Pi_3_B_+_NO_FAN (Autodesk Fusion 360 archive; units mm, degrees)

design "Pi_3_B_+_NO_FAN" references "Pi 3 B + NO_FAN"
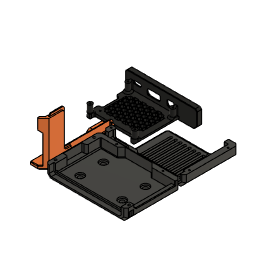
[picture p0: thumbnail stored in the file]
external_derived "ExternalDerived1" bodies "BOTTOM", "Body4", "TOP (1)", "PI3 A/B_MOUNT  (1) (2)"
derived_instance "DerivedInstance1"
derived_instance "DerivedInstance2"
derived_instance "DerivedInstance3"
derived_instance "DerivedInstance1"
derived_instance "DerivedInstance1"
derived_instance "DerivedInstance2"
derived_base_feature "Derived Base Feature1" bodies "BOTTOM"
hole "Hole2" HoleDepth 5 named "d222_1" HoleDiameter 5.3 named "d223_1" CBDepth 2 named "d225_1" CBDiameter 10 named "d226_1" RefDim1 25 named "d227_1" RefDim2 20 named "d228_1"
hole "Hole4" HoleDepth 5 named "d240_1" HoleDiameter 5.3 named "d241_1" CBDepth 2 named "d243_1" CBDiameter 10 named "d244_1" RefDim1 20 named "d245_1" RefDim2 25 named "d246_1"
rectangular_pattern "R-Pattern2" uSpaceDistance 30 named "d249_1" vSpaceDistance 0 named "d250_1"
rectangular_pattern "R-Pattern3" uSpaceDistance 30 named "d253_1" vSpaceDistance 0 named "d254_1"
step "Arrange" envelopeLength 180 envelopeWidth 180 envelopeSeparation 0 separation 5 padding 5 offset 0
extrude "Extrude1" cut of existing geometry blind -1.6248
offset_faces "OffsetFaces1" distance -2.302
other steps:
derived_base_feature "Derived Base Feature1"
derived_base_feature "Derived Base Feature1"
derived_base_feature "Derived Base Feature1" bodies "BOTTOM"
derived_base_feature "Derived Base Feature1" bodies "Body4"
derived_base_feature "Derived Base Feature1" bodies "TOP (1)"
derived_base_feature "Derived Base Feature1" bodies "PI3 A/B_MOUNT  (1) (2)"
create_component "CreateComponent1"
create_component "CreateComponent2"
create_component "CreateComponent3"
create_component "CreateComponent4"
create_component "CreateComponent5"
create_component "CreateComponent6"
create_component "CreateComponent7"
named bodies: "TOP (1)", "BOTTOM", "PI3 A/B_MOUNT  (1) (2)", "Body4"

design "Pi 3 B + NO_FAN"
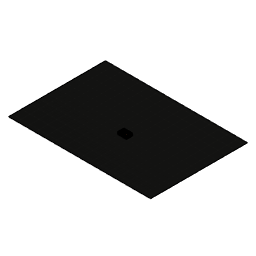
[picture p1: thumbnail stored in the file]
description: arrangementsContainer
base_feature "Base Feature1" bodies "TOP"
base_feature "Base Feature1" bodies "BOTTOM"
base_feature "Base Feature1"
base_feature "Base Feature1"
base_feature "Base Feature1"
base_feature "Base Feature1"
base_feature "Base Feature1"
base_feature "Base Feature1"
base_feature "Base Feature1"
base_feature "Base Feature1"
position "Position1"
sketch "Sketch1" plane through (0, 0, 0) normal (0, 0, 1) x axis (1, 0, 0)
  line L1 (753.1049, -468.8034) -> (-832.4959, -468.8034)
  line L2 (753.1049, 612.7156) -> (753.1049, -468.8034)
  line L3 (-832.4959, 612.7156) -> (753.1049, 612.7156)
  line L4 (-832.4959, -468.8034) -> (-832.4959, 612.7156)
  horizontal L1
  vertical L2
  horizontal L3
  vertical L4
extrude "Extrude1" new body sketch "Sketch1" against normal blind 1
base_feature "Base Feature1" bodies "PI3 A/B_MOUNT  (1) (2)"
component_from_bodies "Body->Comp1"
step "Arrange1" envelopeLength 180 named "d2_1" envelopeWidth 180 envelopeSeparation 0 separation 5 padding 5 offset 0 bodies "TOP"
base_feature "Base Feature1"
position "Position2"
position "Position3"
delete_face "DeleteFace1"
base_feature "Base Feature1" bodies "PI_ZERO_MOUNT_1"
move_face "MoveFace1"
work_plane "WorkPlane2"
split "Split1" bodies "TOP (1)"
move "Move1"
move "Move2"
position "Position4"
align "Align1"
move "Move3"
extrude "Extrude1" add of existing geometry blind 24.193 bodies "TOP (1)"
delete_face "DeleteFace2"
delete_face "DeleteFace3"
delete_face "DeleteFace4"
align "Align1"
work_plane "WorkPlane3"
split "Split1" bodies "BOTTOM (1)"
move "Move1"
align "Align2"
move "Move2"
move "Move3"
extrude "Extrude1" add of existing geometry blind 20.9455 bodies "BOTTOM (1)"
work_plane "WorkPlane4"
split "Split2" bodies "BOTTOM (1)"
delete_face "DeleteFace1"
move "Move4"
split "Split2"
move "Move4"
align "Align3"
align "Align4"
align "Align1"
align "Align1"
delete_face "DeleteFace2"
delete_face "DeleteFace3"
extrude "Extrude2" add of existing geometry blind 28.705 bodies "BOTTOM (1)"
extrude "Extrude2" add of existing geometry blind 27.166 bodies "TOP"
extrude "Extrude3" add of existing geometry blind 29.088
align "Align1"
align "Align2"
align "Align3"
align "Align1"
align "Align1"
align "Align1"
align "Align1"
align "Align1"
work_plane "WorkPlane5" AlongDistance -25
split "Split1"
align "Align4"
extrude "Extrude1" add of existing geometry blind 20.935
move_face "MoveFace1"
move_face "MoveFace2"
move_face "MoveFace2"
delete_face "DeleteFace1"
delete_face "DeleteFace2"
sketch "Sketch3" plane through (0, 0, 18.6752) normal (0, 0, -1) x axis (1, 0, 0)
  line L1 (-40.9922, -30.131) -> (-40.9922, 26.269)
  line L2 (-39.8593, -30.131) -> (-40.9922, -30.131)
  line L3 (-39.8593, -21.931) -> (-39.8593, -30.131)
  line L4 (-37.6593, -19.731) -> (-39.8593, -21.931)
  line L5 (37.1513, -19.731) -> (-37.6593, -19.731)
  line L6 (37.9797, -18.9025) -> (37.1513, -19.731)
  line L7 (37.9797, 16.5519) -> (37.9797, -18.9025)
  line L8 (40.6719, 19.2441) -> (37.9797, 16.5519)
  line L9 (40.6719, 26.269) -> (40.6719, 19.2441)
  line L10 (4.9368, 26.269) -> (40.6719, 26.269)
  line L11 (6.4368, -14.231) -> (6.4368, 24.769)
  line L12 (3.4368, 24.769) -> (3.4368, -14.231)
  line L13 (-0.0632, 26.269) -> (4.9368, 26.269)
  line L14 (1.4368, -14.231) -> (1.4368, 24.769)
  line L15 (-1.5632, 24.769) -> (-1.5632, -14.231)
  line L16 (-5.0632, 26.269) -> (-0.0632, 26.269)
  line L17 (-3.5632, -15.231) -> (-3.5632, 24.769)
  line L18 (-6.5632, 24.769) -> (-6.5632, -15.231)
  line L19 (-10.0633, 26.269) -> (-5.0632, 26.269)
  line L20 (-9.9796, 26.2667) -> (-9.9797, 26.2667)
  line L21 (-8.5632, -17.231) -> (-8.5632, 24.769)
  line L22 (-9.9797, -18.7286) -> (-9.9796, -18.7286)
  line L23 (-11.5633, 24.769) -> (-11.5633, -17.231)
  line L24 (-15.0633, 26.269) -> (-10.0633, 26.269)
  line L25 (-13.5633, -17.231) -> (-13.5633, 24.769)
  line L26 (-16.5633, 24.769) -> (-16.5633, -17.231)
  line L27 (-20.0633, 26.269) -> (-15.0633, 26.269)
  line L28 (-18.5633, -15.231) -> (-18.5633, 24.769)
  line L29 (-21.5633, 24.769) -> (-21.5633, -15.231)
  line L30 (-25.0633, 26.269) -> (-20.0633, 26.269)
  line L31 (-23.5633, -14.231) -> (-23.5633, 24.769)
  line L32 (-26.5633, 24.769) -> (-26.5633, -14.231)
  line L33 (-30.0633, 26.269) -> (-25.0633, 26.269)
  line L34 (-28.5633, -14.231) -> (-28.5633, 24.769)
  line L35 (-31.5633, 24.769) -> (-31.5633, -14.231)
  line L36 (-35.0633, 26.269) -> (-30.0633, 26.269)
  line L37 (-33.5633, -14.231) -> (-33.5633, 24.769)
  line L38 (-36.5633, 24.769) -> (-36.5633, -14.231)
  line L39 (-40.9922, 26.269) -> (-35.0633, 26.269)
  line L40 (-32.6085, -18.7224) -> (10.2712, -18.7224)
  line L41 (-32.6085, 24.769) -> (-32.6085, -18.7224)
  line L42 (10.2712, 24.769) -> (-32.6085, 24.769)
  line L43 (10.2712, -18.7224) -> (10.2712, 24.769)
  arc A1 centre (4.9368, 24.769) radius 1.5 clockwise from (4.9368, 26.269) to (6.4368, 24.769)
  arc A2 centre (4.9368, -14.231) radius 1.5 clockwise from (6.4368, -14.231) to (3.4368, -14.231)
  arc A3 centre (4.9368, 24.769) radius 1.5 clockwise from (3.4368, 24.769) to (4.9368, 26.269)
  arc A4 centre (-0.0632, 24.769) radius 1.5 clockwise from (-0.0632, 26.269) to (1.4368, 24.769)
  arc A5 centre (-0.0632, -14.231) radius 1.5 clockwise from (1.4368, -14.231) to (-1.5632, -14.231)
  arc A6 centre (-0.0632, 24.769) radius 1.5 clockwise from (-1.5632, 24.769) to (-0.0632, 26.269)
  arc A7 centre (-5.0632, 24.769) radius 1.5 clockwise from (-5.0632, 26.269) to (-3.5632, 24.769)
  arc A8 centre (-5.0632, -15.231) radius 1.5 clockwise from (-3.5632, -15.231) to (-6.5632, -15.231)
  arc A9 centre (-5.0632, 24.769) radius 1.5 clockwise from (-6.5632, 24.769) to (-5.0632, 26.269)
  arc A10 centre (-10.0633, 24.769) radius 1.5 clockwise from (-10.0633, 26.269) to (-9.9797, 26.2667)
  arc A11 centre (-10.0632, 24.769) radius 1.5 clockwise from (-9.9796, 26.2667) to (-8.5632, 24.769)
  arc A12 centre (-10.0632, -17.231) radius 1.5 clockwise from (-8.5632, -17.231) to (-9.9796, -18.7286)
  arc A13 centre (-10.0633, -17.231) radius 1.5 clockwise from (-9.9797, -18.7286) to (-11.5633, -17.231)
  arc A14 centre (-10.0633, 24.769) radius 1.5 clockwise from (-11.5633, 24.769) to (-10.0633, 26.269)
  arc A15 centre (-15.0633, 24.769) radius 1.5 clockwise from (-15.0633, 26.269) to (-13.5633, 24.769)
  arc A16 centre (-15.0633, -17.231) radius 1.5 clockwise from (-13.5633, -17.231) to (-16.5633, -17.231)
  arc A17 centre (-15.0633, 24.769) radius 1.5 clockwise from (-16.5633, 24.769) to (-15.0633, 26.269)
  arc A18 centre (-20.0633, 24.769) radius 1.5 clockwise from (-20.0633, 26.269) to (-18.5633, 24.769)
  arc A19 centre (-20.0633, -15.231) radius 1.5 clockwise from (-18.5633, -15.231) to (-21.5633, -15.231)
  arc A20 centre (-20.0633, 24.769) radius 1.5 clockwise from (-21.5633, 24.769) to (-20.0633, 26.269)
  arc A21 centre (-25.0633, 24.769) radius 1.5 clockwise from (-25.0633, 26.269) to (-23.5633, 24.769)
  arc A22 centre (-25.0633, -14.231) radius 1.5 clockwise from (-23.5633, -14.231) to (-26.5633, -14.231)
  arc A23 centre (-25.0633, 24.769) radius 1.5 clockwise from (-26.5633, 24.769) to (-25.0633, 26.269)
  arc A24 centre (-30.0633, 24.769) radius 1.5 clockwise from (-30.0633, 26.269) to (-28.5633, 24.769)
  arc A25 centre (-30.0633, -14.231) radius 1.5 clockwise from (-28.5633, -14.231) to (-31.5633, -14.231)
  arc A26 centre (-30.0633, 24.769) radius 1.5 clockwise from (-31.5633, 24.769) to (-30.0633, 26.269)
  arc A27 centre (-35.0633, 24.769) radius 1.5 clockwise from (-35.0633, 26.269) to (-33.5633, 24.769)
  arc A28 centre (-35.0633, -14.231) radius 1.5 clockwise from (-33.5633, -14.231) to (-36.5633, -14.231)
  arc A29 centre (-35.0633, 24.769) radius 1.5 clockwise from (-36.5633, 24.769) to (-35.0633, 26.269)
  horizontal L40
  vertical L41
  horizontal L42
  vertical L43
extrude "Extrude4" add sketch "Sketch3" profile of L11 A2 L12 L14 A5 L15 L17 A8 L18 L21 A12 A13 L23 L25 A16 L26 L28 A19 L29 L31 A22 L32 L34 A25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 against normal blind 3
delete_face "DeleteFace3"
delete_face "DeleteFace4"
delete_face "DeleteFace5"
delete_face "DeleteFace6"
delete_face "DeleteFace7"
delete_face "DeleteFace8"
rectangular_pattern "R-Pattern1" uSpaceDistance 6 vSpaceDistance 0
position "Position5"
work_plane "WorkPlane6" AlongDistance 2
work_plane "WorkPlane7" AlongDistance 2
move_face "MoveFace1"
move_face "MoveFace2"
move_face "MoveFace3"
hole "Hole1" HoleDepth 10 HoleDiameter 2 RefDim1 3 RefDim2 20
work_axis "WorkAxis1"
move_face "MoveFace4"
work_axis "WorkAxis3"
move_face "MoveFace3"
rectangular_pattern "R-Pattern1" uSpaceDistance 60 vSpaceDistance 0
position "Position6"
position "Position7"
delete_face "DeleteFace1"
delete_face "DeleteFace2"
delete_face "DeleteFace3"
extrude "Extrude2" cut of existing geometry blind -5
delete_face "DeleteFace4"
offset_faces "OffsetFaces1" distance -3.933
offset_faces "OffsetFaces2" distance -1
move_face "MoveFace4"
delete_face "DeleteFace5"
delete_face "DeleteFace4"
delete_face "DeleteFace5"
delete_face "DeleteFace6"
offset_faces "OffsetFaces1" distance -3
delete_face "DeleteFace7"
chamfer "Chamfer2" distance 1
work_plane "WorkPlane8" AlongDistance 1
move_face "MoveFace2"
move_face "MoveFace5"
work_plane "WorkPlane9" AlongDistance 0
sketch "Sketch4" plane through (0, 0, 16.7) normal (0, 0, 1) x axis (-1, 0, 0)
  line L1 (-45.1398, 29) -> (-45.1398, 24.4)
  line L2 (-45.7598, 29) -> (-45.1398, 29)
  line L3 (-45.7598, 35) -> (-45.7598, 29)
  line L4 (-49.1398, 35) -> (-45.7598, 35)
  line L5 (-52.1398, 32) -> (-49.1398, 35)
  line L6 (-52.1398, 21.7542) -> (-52.1398, 32)
  line L7 (-49.1398, 20) -> (-49.1398, 25)
  line L8 (-52.1398, -32) -> (-52.1398, 22.2)
  line L9 (-52.1398, 20) -> (-49.1398, 20)
  line L10 (-45.1398, 20) -> (-45.1398, 24.4)
  line L11 (-49.1398, 20) -> (-45.1398, 20)
  circle C1 centre (-49.1398, 25) radius 1.4
  arc A1 centre (-49.1398, 24.4) radius 4 clockwise from (-45.1398, 24.4) to (-52.1398, 21.7542)
  point P2 (-49.1398, 25)
  point P11 (-49.1398, 25)
  point P15 (-52.1398, 20)
  point P3 (-45.1398, 24.4)
  point P16 (-45.1398, 24.4)
  point P12 (-49.1398, 20)
  coincident P2 P11
  vertical L7
  coincident L8 P15
  perpendicular L8 L9
  coincident P3 P16
  perpendicular L9 L10
  perpendicular L7 L11
  dimension "d48" distance P11 P12 = 5
extrude "Extrude3" add sketch "Sketch4" profile of A1 L7 L10 L11 against normal blind 11.7
offset_faces "OffsetFaces2" distance 3
delete_face "DeleteFace8"
delete_face "DeleteFace9"
move_face "MoveFace6"
delete_face "DeleteFace10"
delete_face "DeleteFace11"
delete_face "DeleteFace12"
move_face "MoveFace7"
work_axis "WorkAxis4"
move_face "MoveFace4"
offset_faces "OffsetFaces1" distance -1.4
chamfer "Chamfer2" distance 3
fillet "Fillet1" radius 2
offset_faces "OffsetFaces3" distance 1.4
offset_faces "OffsetFaces3" distance -1
offset_faces "OffsetFaces4" distance 1
position "Position8"
offset_faces "OffsetFaces1" distance -1
offset_faces "OffsetFaces5" distance -0.4
offset_faces "OffsetFaces3" distance -1.053
sketch "Sketch5" plane through (0, -27, 0) normal (0, 1, 0) x axis (-1, 0, 0)
  line L1 (-40.8321, 30.4) -> (-13.0969, 30.4)
  line L2 (-45.1398, 26.0922) -> (-40.8321, 30.4)
  line L3 (-45.1398, 24.753) -> (-45.1398, 26.0922)
  line L4 (-41.3928, 28.5) -> (-45.1398, 24.753)
  line L5 (39.9036, 28.5) -> (-41.3928, 28.5)
  line L6 (45.1398, 23.2638) -> (39.9036, 28.5)
  line L7 (45.1398, 26.0922) -> (45.1398, 23.2638)
  line L8 (40.8321, 30.4) -> (45.1398, 26.0922)
  line L9 (34.9031, 30.4) -> (40.8321, 30.4)
  line L10 (28.9031, 30.4) -> (34.9031, 30.4)
  line L11 (22.9031, 30.4) -> (28.9031, 30.4)
  line L12 (16.9031, 30.4) -> (22.9031, 30.4)
  line L13 (10.9031, 30.4) -> (16.9031, 30.4)
  line L14 (4.9031, 30.4) -> (10.9031, 30.4)
  line L15 (-1.0969, 30.4) -> (4.9031, 30.4)
  line L16 (-7.0969, 30.4) -> (-1.0969, 30.4)
  line L17 (-13.0969, 30.4) -> (-7.0969, 30.4)
  line L18 (-21.1686, 27.0881) -> (-42.8047, 27.0881)
  line L19 (-21.0388, 27.4) -> (-20.0388, 28.4)
  line L20 (-20.5388, 27.9) -> (-20.0388, 28.4)
  line L21 (-22.4602, 25.9787) -> (-20.5388, 27.9)
  line L22 (-21.0388, 27.4) -> (-22.4602, 25.9787)
  line L23 (-45.1398, 24.753) -> (-41.3928, 28.5)
  line L24 (39.9036, 28.5) -> (-41.3928, 28.5)
  line L25 (-41.4928, 28.4) -> (-20.0388, 28.4)
  point P19 (-42.8047, 27.0881)
  point P21 (-20.0388, 28.4)
  point P28 (-20.0388, 28.4)
  point P29 (-41.4928, 28.4)
  coincident L4 P19
  parallel L5 L18
  coincident P21 P28
  coincident L23 P29
  parallel L24 L25
extrude "Extrude5" add sketch "Sketch5" profile of L4 L18 L19 L20 L21 L22 L23 L25 against normal blind 2
offset_faces "OffsetFaces4" distance 0.172
offset_faces "OffsetFaces5" distance -5
delete_face "DeleteFace9"
offset_faces "OffsetFaces6" distance -2
offset_faces "OffsetFaces7" distance -1
chamfer "Chamfer3" distance 2.5
offset_faces "OffsetFaces6" distance -1
move_face "MoveFace3"
move_face "MoveFace4"
move_face "MoveFace5"
position "Position9"
offset_faces "OffsetFaces4" distance 0.4
sketch "Sketch6" plane through (0, -24.4, 0) normal (0, 1, 0) x axis (-1, 0, 0)
  line L1 (-44.9031, 33.4) -> (-40.0398, 33.4)
  line L2 (-52.1398, 26.1633) -> (-44.9031, 33.4)
  line L3 (-52.1398, 16.7) -> (-52.1398, 26.1633)
  line L4 (-47.1398, 16.7) -> (-52.1398, 16.7)
  line L5 (-47.1398, 26.9206) -> (-47.1398, 16.7)
  line L6 (-43.6605, 30.4) -> (-47.1398, 26.9206)
  line L7 (-38.1398, 30.4) -> (-43.6605, 30.4)
  line L8 (-38.1398, 31.6) -> (-38.1398, 30.4)
  line L9 (-40.0398, 31.6) -> (-38.1398, 31.6)
  line L10 (-40.0398, 33.4) -> (-40.0398, 31.6)
  line L11 (-51.3825, 26.9206) -> (-47.1398, 26.9206)
  line L12 (-47.1398, 29.0252) -> (-42.2068, 29.0252)
  line L13 (-49.2779, 29.0252) -> (-47.1398, 29.0252)
  line L14 (-49.2779, 29.0252) -> (-49.2779, 29.0252)
  line L15 (-42.2068, 29.0252) -> (-49.2779, 29.0252)
  line L16 (-42.2068, 29.0252) -> (-42.2068, 29.0252)
  point P7 (-47.1398, 26.9206)
  point P12 (-47.1398, 26.9206)
  point P13 (-51.3825, 26.9206)
  coincident P7 P12
  coincident L2 P13
  perpendicular L5 L11
extrude "Extrude2" new body sketch "Sketch6" profile of L2 L6 L11 L12 L13 L15 blind 15 from offset 0.1
combine "Combine1"
chamfer "Chamfer3" distance 2
delete_face "DeleteFace6"
offset_faces "OffsetFaces5" distance 0.75
extrude "Extrude3" add of existing geometry blind 1
delete_face "DeleteFace7"
offset_faces "OffsetFaces6" distance -1
extrude "Extrude4" add of existing geometry blind 1
delete_face "DeleteFace8"
delete_face "DeleteFace9"
delete_face "DeleteFace10"
chamfer "Chamfer5" distance 0.75
delete_face "DeleteFace11"
delete_face "DeleteFace12"
delete_face "DeleteFace13"
chamfer "Chamfer6" distance 0.75
offset_faces "OffsetFaces7" distance 0.8
delete_face "DeleteFace14"
chamfer "Chamfer4" distance 0.75
chamfer "Chamfer7" distance 0.75
split "Split3" bodies "TOP (1) (1)", "TOP (1) (2)"
chamfer "Chamfer5" distance 0.75
combine "Combine1" bodies "TOP (1) (1)", "TOP (1) (2)"
draft "Draft1" "d90" 45 (= "Angle1") "d91" 0 (= "Angle2")
combine "Combine2"
offset_faces "OffsetFaces7" distance 0.2
offset_faces "OffsetFaces8" distance -0.2
move_face "MoveFace5"
move_face "MoveFace5"
offset_faces "OffsetFaces9" distance -0.1
chamfer "Chamfer8" distance 2
chamfer "Chamfer3" distance 2
sketch "Sketch7" plane through (0, -24.3, 0) normal (0, -1, 0) x axis (1, 0, 0)
  line L1 (25.1398, 30.4) -> (25.1398, 31.6)
  line L2 (40.8321, 30.4) -> (25.1398, 30.4)
  line L3 (41.2068, 30.0252) -> (40.8321, 30.4)
  line L4 (44.0353, 30.0252) -> (41.2068, 30.0252)
  line L5 (45.0353, 29.0252) -> (44.0353, 30.0252)
  line L6 (47.8898, 26.1706) -> (45.0353, 29.0252)
  line L7 (47.8898, 25.1706) -> (47.8898, 26.1706)
  line L8 (51.3825, 25.1706) -> (47.8898, 25.1706)
  line L9 (52.1325, 25.9206) -> (51.3825, 25.1706)
  line L10 (52.1325, 26.1706) -> (52.1325, 25.9206)
  line L11 (44.9031, 33.4) -> (52.1325, 26.1706)
  line L12 (27.0398, 33.4) -> (44.9031, 33.4)
  line L13 (27.0398, 31.6) -> (27.0398, 33.4)
  line L14 (25.1398, 31.6) -> (27.0398, 31.6)
  line L15 (40.1398, 31.6) -> (25.1398, 31.6)
  line L16 (40.1398, 30.4) -> (40.1398, 31.6)
  line L17 (25.1398, 30.4) -> (40.1398, 30.4)
  line L18 (25.1398, 31.6) -> (25.1398, 30.4)
  point P2 (25.1398, 31.6)
  point P16 (25.1398, 31.6)
  point P17 (40.1398, 31.6)
  horizontal L15
  vertical L16
  horizontal L17
  vertical L18
  coincident P2 P16
  dimension "d97" distance P16 P17 = 15
extrude "Extrude5" add sketch "Sketch7" profile of L1 L2 L14 L15 L16 L17 L18 along normal blind 2
delete_face "DeleteFace15"
delete_face "DeleteFace16"
delete_face "DeleteFace17"
delete_face "DeleteFace18"
offset_faces "OffsetFaces8" distance 0.6
chamfer "Chamfer10" distance 2.6
combine "Combine2"
offset_faces "OffsetFaces10" distance -0.1
offset_faces "OffsetFaces9" distance 2
combine "Combine3"
offset_faces "OffsetFaces11" distance -0.1
offset_faces "OffsetFaces12" distance -0.1
offset_faces "OffsetFaces13" distance -0.1
sketch "Sketch8" plane through (0, -27, 0) normal (0, 1, 0) x axis (-1, 0, 0)
  line L1 (-40.4097, 31.7) -> (-25.0398, 31.7)
  line L2 (-40.4097, 30.4) -> (-40.4097, 31.7)
  line L3 (-43.6605, 30.4) -> (-40.4097, 30.4)
  line L4 (-45.1398, 28.9206) -> (-43.6605, 30.4)
  line L5 (-45.1398, 26.1672) -> (-45.1398, 28.9206)
  line L6 (-44.2189, 27.0881) -> (-45.1398, 26.1672)
  line L7 (-28.4218, 27.0881) -> (-44.2189, 27.0881)
  line L8 (-27.0099, 28.5) -> (-28.4218, 27.0881)
  line L9 (39.9036, 28.5) -> (-27.0099, 28.5)
  line L10 (45.1398, 23.2638) -> (39.9036, 28.5)
  line L11 (45.1398, 26.0922) -> (45.1398, 23.2638)
  line L12 (40.8321, 30.4) -> (45.1398, 26.0922)
  line L13 (34.9031, 30.4) -> (40.8321, 30.4)
  line L14 (28.9031, 30.4) -> (34.9031, 30.4)
  line L15 (22.9031, 30.4) -> (28.9031, 30.4)
  line L16 (16.9031, 30.4) -> (22.9031, 30.4)
  line L17 (10.9031, 30.4) -> (16.9031, 30.4)
  line L18 (4.9031, 30.4) -> (10.9031, 30.4)
  line L19 (-1.0969, 30.4) -> (4.9031, 30.4)
  line L20 (-7.0969, 30.4) -> (-1.0969, 30.4)
  line L21 (-13.0969, 30.4) -> (-7.0969, 30.4)
  line L22 (-25.0398, 30.4) -> (-13.0969, 30.4)
  line L23 (-25.0398, 31.7) -> (-25.0398, 30.4)
  line L24 (-18.6605, 30.4) -> (-43.6605, 30.4)
  line L25 (-18.6605, 28.5) -> (-18.6605, 30.4)
  line L26 (-45.5605, 28.5) -> (-18.6605, 28.5)
  line L27 (-43.6605, 30.4) -> (-45.5605, 28.5)
  point P5 (-43.6605, 30.4)
  point P25 (-43.6605, 30.4)
  point P27 (-18.6605, 28.5)
  point P26 (-18.6605, 30.4)
  coincident P5 P25
  parallel L22 L24
  coincident L9 P27
  perpendicular L9 L25
  perpendicular L5 L26
  parallel L4 L27
  dimension "d108" distance P25 P26 = 25
extrude "Extrude6" add sketch "Sketch8" profile of L3 L4 L5 L9 L22 L24 L25 L26 L27 along normal blind 2.6
delete_face "DeleteFace10"
chamfer "Chamfer4" distance 2.5
delete_face "DeleteFace11"
offset_faces "OffsetFaces14" distance -0.1
sketch "Sketch9" plane through (0, 0, 33.4) normal (0, 0, 1) x axis (-1, 0, 0)
  line L1 (-24.9398, -18.9172) -> (-24.9398, 22.4)
  line L2 (-22.957, -20.9) -> (-24.9398, -18.9172)
  line L3 (36.5406, -20.9) -> (-22.957, -20.9)
  line L4 (39.6992, -24.0586) -> (36.5406, -20.9)
  line L5 (39.6992, -32) -> (39.6992, -24.0586)
  line L6 (44.9031, -32) -> (39.6992, -32)
  line L7 (44.9031, 32) -> (44.9031, -32)
  line L8 (34.6979, 32) -> (44.9031, 32)
  line L9 (34.6979, 31) -> (34.6979, 32)
  line L10 (28.8979, 32) -> (28.8979, 31)
  line L11 (-24.9412, 32) -> (28.8979, 32)
  line L12 (-24.9412, 31) -> (-24.9412, 32)
  line L13 (-30.7412, 32) -> (-30.7412, 31)
  line L14 (-44.9031, 32) -> (-30.7412, 32)
  line L15 (-44.9031, 24.4) -> (-44.9031, 32)
  line L16 (-26.9398, 24.4) -> (-44.9031, 24.4)
  line L17 (-24.9398, 22.4) -> (-26.9398, 24.4)
  line L18 (-9.0969, 25.5) -> (-9.0969, -13.5)
  line L19 (-5.0969, -13.5) -> (-5.0969, 25.5)
  line L20 (2.9031, 25.5) -> (2.9031, -13.5)
  line L21 (6.9031, -13.5) -> (6.9031, 25.5)
  line L22 (14.9031, 25.5) -> (14.9031, -13.5)
  line L23 (18.9031, -13.5) -> (18.9031, 25.5)
  line L24 (26.9031, 25.5) -> (26.9031, -13.5)
  line L25 (30.9031, -13.5) -> (30.9031, 25.5)
  line L26 (36.9031, -13.5) -> (36.9031, 25.5)
  line L27 (32.9031, 25.5) -> (32.9031, -13.5)
  line L28 (20.9031, 25.5) -> (20.9031, -13.5)
  line L29 (24.9031, -13.5) -> (24.9031, 25.5)
  line L30 (8.9031, 25.5) -> (8.9031, -13.5)
  line L31 (12.9031, -13.5) -> (12.9031, 25.5)
  line L32 (-3.0969, 25.5) -> (-3.0969, -13.5)
  line L33 (0.9031, -13.5) -> (0.9031, 25.5)
  line L34 (-15.0969, 25.5) -> (-15.0969, -13.5)
  line L35 (-11.0969, -13.5) -> (-11.0969, 25.5)
  line L36 (32.9031, -13.5) -> (32.9031, 25.5)
  line L37 (36.9031, 25.5) -> (36.9031, -13.5)
  line L38 (34.9031, -8.5) -> (34.9031, -13.5)
  line L39 (36.4031, -13.5) -> (36.4031, 25.5)
  line L40 (36.9031, -8.5) -> (32.9031, -8.5)
  arc A1 centre (31.7979, 31) radius 2.9 clockwise from (34.6979, 31) to (28.8979, 31)
  arc A2 centre (-27.8412, 31) radius 2.9 clockwise from (-24.9412, 31) to (-30.7412, 31)
  arc A3 centre (-7.0969, 25.5) radius 2 clockwise from (-9.0969, 25.5) to (-5.0969, 25.5)
  arc A4 centre (-7.0969, -13.5) radius 2 clockwise from (-5.0969, -13.5) to (-9.0969, -13.5)
  arc A5 centre (4.9031, 25.5) radius 2 clockwise from (2.9031, 25.5) to (6.9031, 25.5)
  arc A6 centre (4.9031, -13.5) radius 2 clockwise from (6.9031, -13.5) to (2.9031, -13.5)
  arc A7 centre (16.9031, 25.5) radius 2 clockwise from (14.9031, 25.5) to (18.9031, 25.5)
  arc A8 centre (16.9031, -13.5) radius 2 clockwise from (18.9031, -13.5) to (14.9031, -13.5)
  arc A9 centre (28.9031, 25.5) radius 2 clockwise from (26.9031, 25.5) to (30.9031, 25.5)
  arc A10 centre (28.9031, -13.5) radius 2 clockwise from (30.9031, -13.5) to (26.9031, -13.5)
  arc A11 centre (34.9031, 25.5) radius 2 clockwise from (32.9031, 25.5) to (36.9031, 25.5)
  arc A12 centre (34.9031, -13.5) radius 2 clockwise from (36.9031, -13.5) to (32.9031, -13.5)
  arc A13 centre (22.9031, 25.5) radius 2 clockwise from (20.9031, 25.5) to (24.9031, 25.5)
  arc A14 centre (22.9031, -13.5) radius 2 clockwise from (24.9031, -13.5) to (20.9031, -13.5)
  arc A15 centre (10.9031, 25.5) radius 2 clockwise from (8.9031, 25.5) to (12.9031, 25.5)
  arc A16 centre (10.9031, -13.5) radius 2 clockwise from (12.9031, -13.5) to (8.9031, -13.5)
  arc A17 centre (-1.0969, 25.5) radius 2 clockwise from (-3.0969, 25.5) to (0.9031, 25.5)
  arc A18 centre (-1.0969, -13.5) radius 2 clockwise from (0.9031, -13.5) to (-3.0969, -13.5)
  arc A19 centre (-13.0969, 25.5) radius 2 clockwise from (-15.0969, 25.5) to (-11.0969, 25.5)
  arc A20 centre (-13.0969, -13.5) radius 2 clockwise from (-11.0969, -13.5) to (-15.0969, -13.5)
  arc A21 centre (34.9031, -13.5) radius 2 clockwise from (36.9031, -13.5) to (32.9031, -13.5)
  circle C1 centre (34.9031, -8.5) radius 2
  circle C2 centre (34.9031, -8.5) radius 1.5
  point P52 (34.9031, -13.5)
  point P82 (34.9031, -13.5)
  point P83 (34.9031, -8.5)
  point P84 (34.9031, -8.5)
  point P85 (34.9031, -8.5)
  point P88 (32.9031, -8.5)
  point P89 (36.9031, -8.5)
  coincident P52 P82
  parallel L26 L38
  coincident P83 P84
  tangent L37 C1
  coincident P83 P85
  tangent C2 L39
  coincident L27 P88
  coincident C1 P88
  coincident L26 P89
  coincident C1 P89
  perpendicular L26 L40
  dimension "d113" distance P82 P83 = 5
extrude "Extrude7" add sketch "Sketch9" profile of L26 A12 L27 A21 L36 L37 C1 C2 L39 L40 against normal blind 3
chamfer "Chamfer5" distance 0.5
sketch "Sketch10" plane through (0, 0, 33.4) normal (0, 0, 1) x axis (-1, 0, 0)
  line L1 (32.9031, 25.5) -> (32.9031, -8.5)
  line L2 (36.9031, -8.5) -> (36.9031, 25.5)
  line L3 (-24.9398, -18.9172) -> (-24.9398, 22.4)
  line L4 (-22.957, -20.9) -> (-24.9398, -18.9172)
  line L5 (36.5406, -20.9) -> (-22.957, -20.9)
  line L6 (39.6992, -24.0586) -> (36.5406, -20.9)
  line L7 (39.6992, -32) -> (39.6992, -24.0586)
  line L8 (44.9031, -32) -> (39.6992, -32)
  line L9 (44.9031, 32) -> (44.9031, -32)
  line L10 (34.6978, 32) -> (44.9031, 32)
  line L11 (34.6978, 31) -> (34.6978, 32)
  line L12 (28.8978, 32) -> (28.8978, 31)
  line L13 (-24.9412, 32) -> (28.8978, 32)
  line L14 (-24.9412, 31) -> (-24.9412, 32)
  line L15 (-30.7412, 32) -> (-30.7412, 31)
  line L16 (-44.9031, 32) -> (-30.7412, 32)
  line L17 (-44.9031, 24.4) -> (-44.9031, 32)
  line L18 (-26.9398, 24.4) -> (-44.9031, 24.4)
  line L19 (-24.9398, 22.4) -> (-26.9398, 24.4)
  line L20 (-9.0969, 25.5) -> (-9.0969, -13.5)
  line L21 (-5.0969, -13.5) -> (-5.0969, 25.5)
  line L22 (2.9031, 25.5) -> (2.9031, -13.5)
  line L23 (6.9031, -13.5) -> (6.9031, 25.5)
  line L24 (14.9031, 25.5) -> (14.9031, -13.5)
  line L25 (18.9031, -13.5) -> (18.9031, 25.5)
  line L26 (26.9031, 25.5) -> (26.9031, -13.5)
  line L27 (30.9031, -13.5) -> (30.9031, 25.5)
  line L28 (20.9031, 25.5) -> (20.9031, -13.5)
  line L29 (24.9031, -13.5) -> (24.9031, 25.5)
  line L30 (8.9031, 25.5) -> (8.9031, -13.5)
  line L31 (12.9031, -13.5) -> (12.9031, 25.5)
  line L32 (-3.0969, 25.5) -> (-3.0969, -13.5)
  line L33 (0.9031, -13.5) -> (0.9031, 25.5)
  line L34 (-15.0969, 25.5) -> (-15.0969, -13.5)
  line L35 (-11.0969, -13.5) -> (-11.0969, 25.5)
  line L36 (34.9031, -15.5) -> (34.9031, -8.5)
  arc A1 centre (34.9031, -8.5) radius 2 clockwise from (36.9031, -8.5) to (32.9031, -8.5)
  arc A2 centre (34.9031, 25.5) radius 2 clockwise from (32.9031, 25.5) to (36.9031, 25.5)
  arc A3 centre (31.7978, 31) radius 2.9 clockwise from (34.6978, 31) to (28.8978, 31)
  arc A4 centre (-27.8412, 31) radius 2.9 clockwise from (-24.9412, 31) to (-30.7412, 31)
  arc A5 centre (-7.0969, 25.5) radius 2 clockwise from (-9.0969, 25.5) to (-5.0969, 25.5)
  arc A6 centre (-7.0969, -13.5) radius 2 clockwise from (-5.0969, -13.5) to (-9.0969, -13.5)
  arc A7 centre (4.9031, 25.5) radius 2 clockwise from (2.9031, 25.5) to (6.9031, 25.5)
  arc A8 centre (4.9031, -13.5) radius 2 clockwise from (6.9031, -13.5) to (2.9031, -13.5)
  arc A9 centre (16.9031, 25.5) radius 2 clockwise from (14.9031, 25.5) to (18.9031, 25.5)
  arc A10 centre (16.9031, -13.5) radius 2 clockwise from (18.9031, -13.5) to (14.9031, -13.5)
  arc A11 centre (28.9031, 25.5) radius 2 clockwise from (26.9031, 25.5) to (30.9031, 25.5)
  arc A12 centre (28.9031, -13.5) radius 2 clockwise from (30.9031, -13.5) to (26.9031, -13.5)
  arc A13 centre (22.9031, 25.5) radius 2 clockwise from (20.9031, 25.5) to (24.9031, 25.5)
  arc A14 centre (22.9031, -13.5) radius 2 clockwise from (24.9031, -13.5) to (20.9031, -13.5)
  arc A15 centre (10.9031, 25.5) radius 2 clockwise from (8.9031, 25.5) to (12.9031, 25.5)
  arc A16 centre (10.9031, -13.5) radius 2 clockwise from (12.9031, -13.5) to (8.9031, -13.5)
  arc A17 centre (-1.0969, 25.5) radius 2 clockwise from (-3.0969, 25.5) to (0.9031, 25.5)
  arc A18 centre (-1.0969, -13.5) radius 2 clockwise from (0.9031, -13.5) to (-3.0969, -13.5)
  arc A19 centre (-13.0969, 25.5) radius 2 clockwise from (-15.0969, 25.5) to (-11.0969, 25.5)
  arc A20 centre (-13.0969, -13.5) radius 2 clockwise from (-11.0969, -13.5) to (-15.0969, -13.5)
  point P4 (34.9031, -8.5)
  point P77 (34.9031, -8.5)
  point P78 (34.9031, -15.5)
  point P79 (34.9031, -15.5)
  coincident P4 P77
  perpendicular L5 L36
  coincident P78 P79
  dimension "d117" distance P77 P78 = 7
hole "Hole1" HoleDepth 2 HoleDiameter 5
extrude "Extrude8" add of existing geometry blind -2 from offset -1
offset_faces "OffsetFaces15" distance 0.5
sketch "Sketch12" plane through (0, 0, 30.4) normal (0, 0, -1) x axis (1, 0, 0)
  line L1 (-36.4031, 25.5) -> (-36.4031, -8.5)
  line L2 (-40.8321, 27) -> (-34.9031, 27)
  line L3 (-40.8321, -29.4) -> (-40.8321, 27)
  line L4 (-39.6992, -29.4) -> (-40.8321, -29.4)
  line L5 (-39.6992, -21.0586) -> (-39.6992, -29.4)
  line L6 (-37.5406, -18.9) -> (-39.6992, -21.0586)
  line L7 (22.27, -18.9) -> (-37.5406, -18.9)
  line L8 (23.0398, -18.1302) -> (22.27, -18.9)
  line L9 (23.0398, 24.4) -> (23.0398, -18.1302)
  line L10 (18.7605, 24.4) -> (23.0398, 24.4)
  line L11 (16.1605, 27) -> (18.7605, 24.4)
  line L12 (13.0969, 27) -> (16.1605, 27)
  line L13 (14.5969, -13.5) -> (14.5969, 25.5)
  line L14 (11.5969, 25.5) -> (11.5969, -13.5)
  line L15 (7.0969, 27) -> (13.0969, 27)
  line L16 (8.5969, -13.5) -> (8.5969, 25.5)
  line L17 (5.5969, 25.5) -> (5.5969, -13.5)
  line L18 (1.0969, 27) -> (7.0969, 27)
  line L19 (2.5969, -13.5) -> (2.5969, 25.5)
  line L20 (-0.4031, 25.5) -> (-0.4031, -13.5)
  line L21 (-4.9031, 27) -> (1.0969, 27)
  line L22 (-3.4031, -13.5) -> (-3.4031, 25.5)
  line L23 (-6.4031, 25.5) -> (-6.4031, -13.5)
  line L24 (-10.9031, 27) -> (-4.9031, 27)
  line L25 (-9.4031, -13.5) -> (-9.4031, 25.5)
  line L26 (-12.4031, 25.5) -> (-12.4031, -13.5)
  line L27 (-16.9031, 27) -> (-10.9031, 27)
  line L28 (-15.4031, -13.5) -> (-15.4031, 25.5)
  line L29 (-18.4031, 25.5) -> (-18.4031, -13.5)
  line L30 (-22.9031, 27) -> (-16.9031, 27)
  line L31 (-21.4031, -13.5) -> (-21.4031, 25.5)
  line L32 (-24.4031, 25.5) -> (-24.4031, -13.5)
  line L33 (-28.9031, 27) -> (-22.9031, 27)
  line L34 (-27.4031, -13.5) -> (-27.4031, 25.5)
  line L35 (-30.4031, 25.5) -> (-30.4031, -13.5)
  line L36 (-34.9031, 27) -> (-28.9031, 27)
  line L37 (-33.4031, -8.5) -> (-33.4031, 25.5)
  line L38 (-31.9031, -15.5) -> (-34.9031, -15.5)
  line L39 (-31.9031, -18.5) -> (-31.9031, -15.5)
  line L40 (-37.9031, -18.5) -> (-31.9031, -18.5)
  line L41 (-37.9031, -15.5) -> (-37.9031, -18.5)
  circle C1 centre (-34.9031, -15.5) radius 3
  arc A1 centre (-34.9031, 25.5) radius 1.5 clockwise from (-36.4031, 25.5) to (-34.9031, 27)
  arc A2 centre (13.0969, 25.5) radius 1.5 clockwise from (13.0969, 27) to (14.5969, 25.5)
  arc A3 centre (13.0969, -13.5) radius 1.5 clockwise from (14.5969, -13.5) to (11.5969, -13.5)
  arc A4 centre (13.0969, 25.5) radius 1.5 clockwise from (11.5969, 25.5) to (13.0969, 27)
  arc A5 centre (7.0969, 25.5) radius 1.5 clockwise from (7.0969, 27) to (8.5969, 25.5)
  arc A6 centre (7.0969, -13.5) radius 1.5 clockwise from (8.5969, -13.5) to (5.5969, -13.5)
  arc A7 centre (7.0969, 25.5) radius 1.5 clockwise from (5.5969, 25.5) to (7.0969, 27)
  arc A8 centre (1.0969, 25.5) radius 1.5 clockwise from (1.0969, 27) to (2.5969, 25.5)
  arc A9 centre (1.0969, -13.5) radius 1.5 clockwise from (2.5969, -13.5) to (-0.4031, -13.5)
  arc A10 centre (1.0969, 25.5) radius 1.5 clockwise from (-0.4031, 25.5) to (1.0969, 27)
  arc A11 centre (-4.9031, 25.5) radius 1.5 clockwise from (-4.9031, 27) to (-3.4031, 25.5)
  arc A12 centre (-4.9031, -13.5) radius 1.5 clockwise from (-3.4031, -13.5) to (-6.4031, -13.5)
  arc A13 centre (-4.9031, 25.5) radius 1.5 clockwise from (-6.4031, 25.5) to (-4.9031, 27)
  arc A14 centre (-10.9031, 25.5) radius 1.5 clockwise from (-10.9031, 27) to (-9.4031, 25.5)
  arc A15 centre (-10.9031, -13.5) radius 1.5 clockwise from (-9.4031, -13.5) to (-12.4031, -13.5)
  arc A16 centre (-10.9031, 25.5) radius 1.5 clockwise from (-12.4031, 25.5) to (-10.9031, 27)
  arc A17 centre (-16.9031, 25.5) radius 1.5 clockwise from (-16.9031, 27) to (-15.4031, 25.5)
  arc A18 centre (-16.9031, -13.5) radius 1.5 clockwise from (-15.4031, -13.5) to (-18.4031, -13.5)
  arc A19 centre (-16.9031, 25.5) radius 1.5 clockwise from (-18.4031, 25.5) to (-16.9031, 27)
  arc A20 centre (-22.9031, 25.5) radius 1.5 clockwise from (-22.9031, 27) to (-21.4031, 25.5)
  arc A21 centre (-22.9031, -13.5) radius 1.5 clockwise from (-21.4031, -13.5) to (-24.4031, -13.5)
  arc A22 centre (-22.9031, 25.5) radius 1.5 clockwise from (-24.4031, 25.5) to (-22.9031, 27)
  arc A23 centre (-28.9031, 25.5) radius 1.5 clockwise from (-28.9031, 27) to (-27.4031, 25.5)
  arc A24 centre (-28.9031, -13.5) radius 1.5 clockwise from (-27.4031, -13.5) to (-30.4031, -13.5)
  arc A25 centre (-28.9031, 25.5) radius 1.5 clockwise from (-30.4031, 25.5) to (-28.9031, 27)
  arc A26 centre (-34.9031, 25.5) radius 1.5 clockwise from (-34.9031, 27) to (-33.4031, 25.5)
  arc A27 centre (-34.9031, -8.5) radius 1.5 clockwise from (-33.4031, -8.5) to (-36.4031, -8.5)
  point P2 (-34.9031, -15.5)
  point P76 (-34.9031, -15.5)
  point P77 (-31.9031, -15.5)
  point P80 (-37.9031, -15.5)
  point P81 (-37.9031, -15.5)
  coincident P2 P76
  coincident C1 P77
  tangent C1 L39
  perpendicular L39 L40
  coincident P80 P81
  tangent C1 L41
  perpendicular L40 L41
  horizontal L40
  tangent C1 L40
extrude "Extrude9" add sketch "Sketch12" profile of C1 L39 L40 L41 along normal blind 2
offset_faces "OffsetFaces17" distance 0.4
offset_faces "OffsetFaces18" distance 0.5
chamfer "Chamfer6" distance 1
hole "Hole2" HoleDepth 3 HoleDiameter 2.8
hole "Hole2" HoleDepth 7.375 HoleDiameter 2
sketch "Sketch13" plane through (0, 0, 31.4) normal (0, 0, 1) x axis (-1, 0, 0)
  line L1 (33.5031, -16.9) -> (36.3031, -16.9)
  line L2 (33.5031, -14.1) -> (33.5031, -16.9)
  line L3 (36.3031, -14.1) -> (33.5031, -14.1)
  line L4 (36.3031, -16.9) -> (36.3031, -14.1)
  line L5 (33.5031, -14.1) -> (36.3031, -16.9)
  line L6 (36.3031, -14.1) -> (33.5031, -16.9)
  line L7 (32.4031, -16.9) -> (37.4031, -16.9)
  line L8 (32.4031, -14.1) -> (32.4031, -16.9)
  line L9 (37.4031, -14.1) -> (32.4031, -14.1)
  line L10 (37.4031, -16.9) -> (37.4031, -14.1)
  line L11 (32.4031, -14.1) -> (37.4031, -16.9)
  line L12 (37.4031, -14.1) -> (32.4031, -16.9)
  circle C1 centre (34.9031, -15.5) radius 1.4
  circle C2 centre (34.9031, -15.5) radius 2.5
  point P7 (34.9031, -15.5)
  point P2 (34.9031, -15.5)
  point P12 (34.9031, -15.5)
  point P5 (33.5031, -14.1)
  point P6 (36.3031, -14.1)
  point P4 (33.5031, -16.9)
  point P10 (32.4031, -14.1)
  point P11 (37.4031, -14.1)
  point P9 (32.4031, -16.9)
  horizontal L1
  perpendicular L1 L2
  parallel L1 L3
  parallel L2 L4
  coincident L5 P7
  coincident L6 P7
  coincident P2 P7
  horizontal L7
  perpendicular L7 L8
  parallel L7 L9
  parallel L8 L10
  coincident L11 P12
  coincident L12 P12
  coincident P7 P12
  dimension "d143" distance P5 P6 = 2.8
  dimension "d144" distance P4 P5 = 2.8
  dimension "d145" distance P10 P11 = 5
  dimension "d146" distance P9 P10 = 2.8
extrude "Extrude10" cut sketch "Sketch13" profile of C1 L1 L2 L3 L4 L7 L9 against normal blind 0.4
extrude "Extrude11" cut sketch "Sketch13" profile of C2 L2 L4 L7 L9 against normal blind 0.2
copy_paste "CopyPaste1"
chamfer "Chamfer7" distance 0.4
chamfer "Chamfer6" distance 0.3
sketch "Sketch14" plane through (0, 0, 31.7) normal (0, 0, -1) x axis (1, 0, 0)
  line L1 (43.0097, 24.4) -> (26.9398, 24.4)
  line L2 (40.4097, 27) -> (43.0097, 24.4)
  line L3 (25.0398, 27) -> (40.4097, 27)
  line L4 (23.0398, 25) -> (25.0398, 27)
  line L5 (23.0398, -18.1302) -> (23.0398, 25)
  line L6 (22.27, -18.9) -> (23.0398, -18.1302)
  line L7 (-37.4031, -18.9) -> (22.27, -18.9)
  line L8 (-37.4719, -18.8313) -> (-37.4031, -18.9)
  line L9 (-39.6992, -21.0586) -> (-37.4719, -18.8313)
  line L10 (-39.6992, -24.0586) -> (-39.6992, -21.0586)
  line L11 (-36.5406, -20.9) -> (-39.6992, -24.0586)
  line L12 (22.957, -20.9) -> (-36.5406, -20.9)
  line L13 (24.9398, -18.9172) -> (22.957, -20.9)
  line L14 (24.9398, 22.4) -> (24.9398, -18.9172)
  line L15 (26.9398, 24.4) -> (24.9398, 22.4)
  line L16 (15.8219, -19) -> (15.8219, -25.269)
  line L17 (-35.8171, -25.269) -> (-35.8171, -19)
  line L18 (-35.8171, -19) -> (-35.8171, -25.269)
  line L19 (15.8219, -19) -> (-35.8171, -19)
  line L20 (15.8219, -25.269) -> (15.8219, -19)
  line L21 (-32.8171, -28.269) -> (12.8219, -28.269)
  line L22 (-36.5406, -20.9) -> (22.957, -20.9)
  arc A1 centre (-32.8171, -25.269) radius 3 clockwise from (-32.8171, -28.269) to (-35.8171, -25.269)
  arc A2 centre (12.8219, -25.269) radius 3 clockwise from (15.8219, -25.269) to (12.8219, -28.269)
extrude "Extrude12" add sketch "Sketch14" profile of L12 L16 L17 L18 L19 L20 L22 along normal blind 0.4
offset_faces "OffsetFaces19" distance -0.2
offset_faces "OffsetFaces20" distance -0.2
base_feature "Base Feature1"
position "Position10"
offset_faces "OffsetFaces21" distance 0.399
position "Position11"
position "Position12"
position "Position13"
position "Position14"
position "Position15"
base_feature "Base Feature1" bodies "PI3 A/B_MOUNT  (1) (2)"
component_from_bodies "Body->Comp1"
step "Arrange1" envelopeLength 180 named "d2_1_1" envelopeWidth 180 named "d3_1" envelopeSeparation 0 named "d4_1" separation 5 named "d6_1" padding 5 named "d7_1" offset 0 named "d8_1" bodies "TOP"
position "Position2"
delete_face "DeleteFace1"
move_face "MoveFace1"
delete_face "DeleteFace2"
delete_face "DeleteFace3"
delete_face "DeleteFace4"
position "Position5"
move_face "MoveFace2"
offset_faces "OffsetFaces1" distance -1 named "d59_1"
move_face "MoveFace3"
move_face "MoveFace4"
move_face "MoveFace5"
hole "Hole1" HoleDepth 3 named "d137_1" HoleDiameter 2.8 named "d138_1"
hole "Hole2" HoleDepth 7.375 named "d140_1" HoleDiameter 2 named "d141_1"
extrude "Extrude1" cut blind -4.3752 named "d178_1"
extrude "Extrude2" add blind -4.3752 named "d181_1" Side1WallThickness 1.1 named "d180_1"
delete_face "DeleteFace5"
offset_faces "OffsetFaces2" distance -0.1 named "d183_1"
chamfer "Chamfer1" distance 1 named "d184_1"
offset_faces "OffsetFaces3" distance -2.291 named "d185_1"
fillet "Fillet1" radius 4 named "d187_1"
move_face "MoveFace6"
delete_face "DeleteFace6"
delete_face "DeleteFace7"
delete_face "DeleteFace8"
delete_face "DeleteFace9"
extrude "Extrude3" cut of existing geometry blind -1.625 named "d188_1"
offset_faces "OffsetFaces4" distance 0 named "d190_1"
delete_face "DeleteFace10"
delete_face "DeleteFace11"
extrude "Extrude4" add of existing geometry blind 10.23 named "d191_1"
move_face "MoveFace8"
move_face "MoveFace9"
hole "Hole3" HoleDepth 10 named "d193_1" HoleDiameter 2 named "d194_1"
hole "Hole4" HoleDepth 10 named "d196_1" HoleDiameter 2 named "d197_1"
hole "Hole5" HoleDepth 10 named "d199_1" HoleDiameter 2 named "d200_1"
hole "Hole6" HoleDepth 10 named "d202_1" HoleDiameter 2 named "d203_1"
offset_faces "OffsetFaces5" distance 1 named "d205_1"
offset_faces "OffsetFaces6" distance 1 named "d244_1"
hole "Hole7" HoleDepth 6.4 named "d250_1" HoleDiameter 2 named "d251_1"
work_axis "WorkAxis5"
work_axis "WorkAxis6"
move_face "MoveFace6"
position "Position16"
align "Align2"
align "Align2"
align "Align2"
align "Align3"
position "Position17"
align "Align4"
sketch "Sketch15" plane through (0, 0, 28.4) normal (0, 0, 1) x axis (-1, 0, 0)
  line L1 (42.8321, 29.5) -> (42.125, 29)
  line L2 (42.8321, 35) -> (42.8321, 29.5)
  line L3 (-41.3524, 35) -> (42.8321, 35)
  line L4 (-41.3524, 29.5) -> (-41.3524, 35)
  line L5 (-20.0388, 29.5) -> (-41.3524, 29.5)
  line L6 (-20.0388, -26.6201) -> (-20.0388, 29.5)
  line L7 (-16.9602, -22.3427) -> (-16.9602, -26.6671)
  line L8 (-15.3744, -20.7569) -> (-16.9602, -22.3427)
  line L9 (35.0541, -20.7569) -> (-15.3744, -20.7569)
  line L10 (36.6398, -22.3427) -> (35.0541, -20.7569)
  line L11 (36.6398, -26.6671) -> (36.6398, -22.3427)
  line L12 (39.7185, -11.482) -> (39.7185, -26.6201)
  line L13 (38.3561, -11.482) -> (39.7185, -11.482)
  line L14 (36.2703, -9.3962) -> (38.3561, -11.482)
  line L15 (36.2703, 10.8322) -> (36.2703, -9.3962)
  line L16 (38.3561, 12.918) -> (36.2703, 10.8322)
  line L17 (39.7185, 12.918) -> (38.3561, 12.918)
  line L18 (39.7185, 29) -> (39.7185, 12.918)
  line L19 (42.125, 29) -> (39.7185, 29)
  line L20 (-1.9699, 15.2588) -> (-3.4133, 17.7588)
  line L21 (-3.4133, 12.7588) -> (-1.9699, 15.2588)
  line L22 (-6.3, 12.7588) -> (-3.4133, 12.7588)
  line L23 (-7.7434, 15.2588) -> (-6.3, 12.7588)
  line L24 (-6.3, 17.7588) -> (-7.7434, 15.2588)
  line L25 (-3.4133, 17.7588) -> (-6.3, 17.7588)
  line L26 (-11.323, 14.8588) -> (-12.7664, 12.3588)
  line L27 (-8.4362, 14.8588) -> (-11.323, 14.8588)
  line L28 (-6.9929, 12.3588) -> (-8.4362, 14.8588)
  line L29 (-8.4362, 9.8588) -> (-6.9929, 12.3588)
  line L30 (-11.323, 9.8588) -> (-8.4362, 9.8588)
  line L31 (-12.7664, 12.3588) -> (-11.323, 9.8588)
  line L32 (-2.7205, 18.1588) -> (-1.2771, 15.6588)
  line L33 (-1.2771, 20.6588) -> (-2.7205, 18.1588)
  line L34 (1.6097, 20.6588) -> (-1.2771, 20.6588)
  line L35 (3.053, 18.1588) -> (1.6097, 20.6588)
  line L36 (1.6097, 15.6588) -> (3.053, 18.1588)
  line L37 (-1.2771, 15.6588) -> (1.6097, 15.6588)
  line L38 (-8.4362, 15.6588) -> (-6.9929, 18.1588)
  line L39 (-11.323, 15.6588) -> (-8.4362, 15.6588)
  line L40 (-12.7664, 18.1588) -> (-11.323, 15.6588)
  line L41 (-11.323, 20.6588) -> (-12.7664, 18.1588)
  line L42 (-8.4362, 20.6588) -> (-11.323, 20.6588)
  line L43 (-6.9929, 18.1588) -> (-8.4362, 20.6588)
  line L44 (8.076, 15.2588) -> (6.6326, 17.7588)
  line L45 (6.6326, 12.7588) -> (8.076, 15.2588)
  line L46 (3.7458, 12.7588) -> (6.6326, 12.7588)
  line L47 (2.3025, 15.2588) -> (3.7458, 12.7588)
  line L48 (3.7458, 17.7588) -> (2.3025, 15.2588)
  line L49 (6.6326, 17.7588) -> (3.7458, 17.7588)
  line L50 (7.3254, 12.3588) -> (8.7688, 9.8588)
  line L51 (8.7688, 14.8588) -> (7.3254, 12.3588)
  line L52 (11.6555, 14.8588) -> (8.7688, 14.8588)
  line L53 (13.0989, 12.3588) -> (11.6555, 14.8588)
  line L54 (11.6555, 9.8588) -> (13.0989, 12.3588)
  line L55 (8.7688, 9.8588) -> (11.6555, 9.8588)
  line L56 (18.8147, 9.0588) -> (17.3713, 6.5588)
  line L57 (21.7014, 9.0588) -> (18.8147, 9.0588)
  line L58 (23.1448, 6.5588) -> (21.7014, 9.0588)
  line L59 (21.7014, 4.0588) -> (23.1448, 6.5588)
  line L60 (18.8147, 4.0588) -> (21.7014, 4.0588)
  line L61 (17.3713, 6.5588) -> (18.8147, 4.0588)
  line L62 (23.8376, -5.4412) -> (22.3943, -7.9412)
  line L63 (26.7244, -5.4412) -> (23.8376, -5.4412)
  line L64 (28.1678, -7.9412) -> (26.7244, -5.4412)
  line L65 (26.7244, -10.4412) -> (28.1678, -7.9412)
  line L66 (23.8376, -10.4412) -> (26.7244, -10.4412)
  line L67 (22.3943, -7.9412) -> (23.8376, -10.4412)
  line L68 (13.7917, 0.3588) -> (12.3484, -2.1412)
  line L69 (16.6785, 0.3588) -> (13.7917, 0.3588)
  line L70 (18.1219, -2.1412) -> (16.6785, 0.3588)
  line L71 (16.6785, -4.6412) -> (18.1219, -2.1412)
  line L72 (13.7917, -4.6412) -> (16.6785, -4.6412)
  line L73 (12.3484, -2.1412) -> (13.7917, -4.6412)
  line L74 (1.6097, 3.2588) -> (-1.2771, 3.2588)
  line L75 (3.053, 0.7588) -> (1.6097, 3.2588)
  line L76 (1.6097, -1.7412) -> (3.053, 0.7588)
  line L77 (-1.2771, -1.7412) -> (1.6097, -1.7412)
  line L78 (-2.7205, 0.7588) -> (-1.2771, -1.7412)
  line L79 (-1.2771, 3.2588) -> (-2.7205, 0.7588)
  line L80 (-6.3, 11.9588) -> (-7.7434, 9.4588)
  line L81 (-3.4133, 11.9588) -> (-6.3, 11.9588)
  line L82 (-1.9699, 9.4588) -> (-3.4133, 11.9588)
  line L83 (-3.4133, 6.9588) -> (-1.9699, 9.4588)
  line L84 (-6.3, 6.9588) -> (-3.4133, 6.9588)
  line L85 (-7.7434, 9.4588) -> (-6.3, 6.9588)
  line L86 (-8.4362, -2.5412) -> (-11.323, -2.5412)
  line L87 (-6.9929, -5.0412) -> (-8.4362, -2.5412)
  line L88 (-8.4362, -7.5412) -> (-6.9929, -5.0412)
  line L89 (-11.323, -7.5412) -> (-8.4362, -7.5412)
  line L90 (-12.7664, -5.0412) -> (-11.323, -7.5412)
  line L91 (-11.323, -2.5412) -> (-12.7664, -5.0412)
  line L92 (-6.3, -11.2412) -> (-7.7434, -13.7412)
  line L93 (-3.4133, -11.2412) -> (-6.3, -11.2412)
  line L94 (-1.9699, -13.7412) -> (-3.4133, -11.2412)
  line L95 (-2.4276, -14.534) -> (-1.9699, -13.7412)
  line L96 (-7.2857, -14.534) -> (-2.4276, -14.534)
  line L97 (-7.7434, -13.7412) -> (-7.2857, -14.534)
  line L98 (3.7458, -5.4412) -> (2.3025, -7.9412)
  line L99 (6.6326, -5.4412) -> (3.7458, -5.4412)
  line L100 (8.076, -7.9412) -> (6.6326, -5.4412)
  line L101 (6.6326, -10.4412) -> (8.076, -7.9412)
  line L102 (3.7458, -10.4412) -> (6.6326, -10.4412)
  line L103 (2.3025, -7.9412) -> (3.7458, -10.4412)
  line L104 (22.3943, -13.7412) -> (22.852, -14.534)
  line L105 (23.8376, -11.2412) -> (22.3943, -13.7412)
  line L106 (26.7244, -11.2412) -> (23.8376, -11.2412)
  line L107 (28.1678, -13.7412) -> (26.7244, -11.2412)
  line L108 (27.71, -14.534) -> (28.1678, -13.7412)
  line L109 (22.852, -14.534) -> (27.71, -14.534)
  line L110 (18.8147, 20.6588) -> (17.3713, 18.1588)
  line L111 (21.7014, 20.6588) -> (18.8147, 20.6588)
  line L112 (23.1448, 18.1588) -> (21.7014, 20.6588)
  line L113 (21.7014, 15.6588) -> (23.1448, 18.1588)
  line L114 (18.8147, 15.6588) -> (21.7014, 15.6588)
  line L115 (17.3713, 18.1588) -> (18.8147, 15.6588)
  line L116 (28.8606, 14.8588) -> (27.4172, 12.3588)
  line L117 (31.7473, 14.8588) -> (28.8606, 14.8588)
  line L118 (33.1907, 12.3588) -> (31.7473, 14.8588)
  line L119 (31.7473, 9.8588) -> (33.1907, 12.3588)
  line L120 (28.8606, 9.8588) -> (31.7473, 9.8588)
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hole "Hole3" HoleDepth 7.4 HoleDiameter 2
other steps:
base_feature "Base Feature1" bodies "PI3 A/B_MOUNT  (1) (2)"
move_face "MoveFace3"
offset_faces "OffsetFaces2" distance -0.4
chamfer "Chamfer2" distance 0.75
base_feature "Base Feature1" bodies "PI3 A/B_MOUNT  (1) (2)"
create_component "CreateComponent1"
create_component "CreateComponent1"
create_component "CreateComponent2"
create_component "CreateComponent2"
create_component "CreateComponent3"
create_component "CreateComponent4"
create_component "CreateComponent5"
create_component "CreateComponent6"
create_component "CreateComponent7"
create_component "CreateComponent8"
create_component "CreateComponent9"
create_component "CreateComponent10"
create_component "CreateComponent1"
remove_body "RemoveBody1"
create_component "CreateComponent11"
create_component "CreateComponent12"
remove_body "RemoveBody1"
hole "Hole1" HoleDepth 3 HoleDiameter 2.8
create_component "CreateComponent13"
create_component "CreateComponent1"
remove_body "RemoveBody1"
create_component "CreateComponent14"
named bodies: "TOP", "BOTTOM", "PI3 A/B_MOUNT  (1) (2)", "PI_ZERO_MOUNT_1", "TOP (1)", "BOTTOM (1)", "TOP (1) (1)", "TOP (1) (2)"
